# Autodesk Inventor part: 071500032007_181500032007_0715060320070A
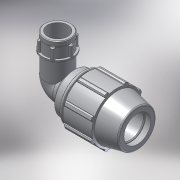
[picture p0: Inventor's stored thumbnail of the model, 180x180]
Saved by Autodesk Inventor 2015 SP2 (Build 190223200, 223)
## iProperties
Created: 2017-02
Part Number: 071500032007_181500032007_0715060320070A
Material: PVC-Piping
Description: PLASSON 90° ELBOW FEMALE ADAPTOR 32-3/4"
Document SubType Name: Modeling
Designer: KIM
Mass: 92.6774 g
Surface Area: 199.44 cm^2
Volume: 66.1981 cm^3
Density: 1.4 g/cm^3
Appearance: Smooth - White
Author: KIM
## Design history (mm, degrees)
derived "07150.ipt"
feature "Solid1::07150.ipt"
tag "TaggingFeature1"
body "Solid1"
other parameters: "d2" = 32, "d4" = 7.91667, "d5" = 23.75, "d7" = 64, "d9" = 13.57143, "d11" = 3.16667, "d13" = 120 deg, "d14" = 44.8, "d15" = 12 deg, "d16" = 55.68, "d18" = 1.6, "d19" = 35 deg, "d20" = 17.5 deg, "d21" = 59.52, "d23" = 0, "d25" = 360 deg, "d27" = 1.28, "d33" = 0.64, "d42" = 35.15, "d43" = 1.92, "d46" = 0.96, "d51" = 95, "d68" = 3.16667, "d72" = 54, "d73" = 31.3521, "d74" = 18, "d75" = 36.05492, "d76" = 24.117, "d77" = 19.8, "d79" = 9.6468, "d80" = 0.72351, "d83" = 0, "d84" = 0, "d91" = 48, "d93" = 67, "d94" = 24.117, "d95" = 16.8819, "d96" = 9.5, "d97" = 50 deg, "d98" = 21.7053, "d99" = 0.5, "d100" = 0.5, "d101" = 6, "d102" = 31.3521, "d103" = 15.3, "d104" = 0, "d108" = 360 deg, "d110" = 0.94056, "d_" = 32, "E_" = 64, "A_" = 95, "l_" = 67, "l_2" = 18, "A_1" = 54, "Rp_" = 24.117, "d105" = 4.70281
